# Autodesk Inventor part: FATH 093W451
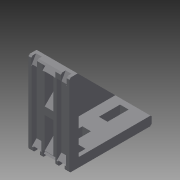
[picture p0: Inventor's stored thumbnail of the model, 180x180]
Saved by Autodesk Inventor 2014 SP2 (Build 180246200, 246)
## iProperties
Created: 2018-10
Part Number: FATH 093W451
Material: Generic
Catalog Web Link: www.cadenas.de
Description: Alu Connection Angle 45-Die-cast Aluminium, Profile 45 and up
Vendor: FATH
Document SubType Name: Modeling
Designer: psadmin
Manufacturer: FATH
Mass: 59.1703 g
Surface Area: 273.577 cm^2
Volume: 59.1703 cm^3
Density: 1 g/cm^3
Appearance: PSOLRGB-175-175-175
Category: PARTsolutions
Company: FATH
Title: FATH 093W451
Author: Cadenas PARTsolutions
Comments: Die-cast Aluminium, Profile 45 and up
PSOL_IDENT_0: {$CADENAS_DATA\23d-libs\fath\zubehoer_alu_sys\aluwinkel\093w451.prj},173 {VTYP=3D},{NB=FATH 093W451}
PSOL_IDENT_1: ,{LINA=FATH 093W451},{NN=Alu Connection Angle 45},{DATE=19.02.2018 15:31:06},{GEOMDATE=21.03.2005},{
PSOL_IDENT_2: VERSION=},{LINEID=570},{WBVAR=},{WBNUMERIC=}  {NB=FATH 093W451},{LINA=FATH 093W451},{KT=DUMMY},{G=Al
PSOL_IDENT_3: uwinkel 86x86x43},{N=ohne},{ARTNR=093W451},{PRTNO=},{NL=0},{NH=0.0},{NHA=0.0}
NN: Aluwinkel 45
NT: Aluminiumdruckguss, ab Profil 45
NB: FATH 093W451
NBSYN: FATH $ARTNR.
LINA: FATH 093W451
G: Aluwinkel 86x86x43
N: ohne
ARTNR: 093W451
SUPPLIER: FATH
ARTICLENO: FATH 093W451
BOMINFO: FATH 093W451
CREATOR: CADENAS GmbH
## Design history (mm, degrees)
sketch "Skizze_1"
  geometry: L1 (8.5, 86)-(1.5, 86); L2 (1.5, 86)-(0, 84.5); L3 (0, 84.5)-(0, 1.5); L4 (1.5, 0)-(84.5, 0); L5 (84.5, 0)-(86, 1.5); L6 (86, 1.5)-(86, 8.5); L7 (86, 8.5)-(8.5, 86); A1 r 1.5 centre (1.5, 1.5) between (0, 1.5) and (1.5, 0)
  constraints: 14 end point, 2 point on circle, 1 centre point
extrude "Extrusion1" join sketch "Skizze_1" stored distance "d0" = 43; taper "d1" = 0 deg
sketch "Skizze_12"
  geometry: L1 (-86, 9.5)-(-10.5, 9.5); L2 (-9.5, 10.5)-(-9.5, 86); L3 (-9.5, 86)-(-86, 9.5); A1 r 1 centre (-10.5, 10.5) between (-10.5, 9.5) and (-9.5, 10.5)
  constraints: 6 end point, 2 point on circle, 1 centre point
extrude "Extrusion2" cut sketch "Skizze_12" distance "d2" = 37; taper "d3" = 0 deg
sketch "Skizze_3"
  geometry: L1 (-2, 79)-(-2, -2); L2 (-2, -2)-(79, -2); L3 (79, -2)-(79, 9.5); L4 (79, 9.5)-(56.876, 9.5); L5 (56.876, 9.5)-(46.376, -1); L6 (46.376, -1)-(39.5, -1); L7 (39.5, -1)-(39.5, 9.5); L8 (39.5, 9.5)-(16.571, 9.5); L9 (16.571, 9.5)-(6.071, -1); L10 (6.071, -1)-(-1, -1); L11 (-1, -1)-(-1, 6.071); L12 (-1, 6.071)-(9.5, 16.571); L13 (9.5, 16.571)-(9.5, 39.5); L14 (9.5, 39.5)-(-1, 39.5); L15 (-1, 39.5)-(-1, 46.376); L16 (-1, 46.376)-(9.5, 56.876); L17 (9.5, 56.876)-(9.5, 79); L18 (9.5, 79)-(-2, 79)
  constraints: 36 end point
extrude "Extrusion3" cut sketch "Skizze_3" stored distance "d4" = 9; taper "d5" = 0 deg
sketch "Skizze_4"
  geometry: L1 (0, 6.788)-(0, 0); L2 (0, 0)-(6.788, 0); L3 (6.788, 0)-(4.101, 2.687); L4 (4.101, 2.687)-(2.687, 1.273); L5 (2.687, 1.273)-(1.273, 2.687); L6 (1.273, 2.687)-(2.687, 4.101); L7 (2.687, 4.101)-(0, 6.788)
  constraints: 14 end point
extrude "Extrusion4" cut sketch "Skizze_4" stored distance "d6" = 13.5; taper "d7" = 0 deg
sketch "Skizze_5"
  geometry: L1 (0, 84.5)-(-4, 84.5); L2 (-4, 84.5)-(-4, -4); L3 (-4, -4)-(84.5, -4); L4 (84.5, -4)-(84.5, 0); L5 (84.5, 0)-(81.672, 2.828); L6 (81.672, 2.828)-(76.843, -2); L7 (76.843, -2)-(-2, -2); L8 (-2, -2)-(-2, 76.843); L9 (-2, 76.843)-(2.828, 81.672); L10 (2.828, 81.672)-(0, 84.5)
  constraints: 20 end point
extrude "Extrusion5" cut sketch "Skizze_5" stored distance "d8" = 13.5; taper "d9" = 0 deg
sketch "Skizze_2"
  geometry: L1 (-20.814, 9.5)-(-9.5, 9.5); L2 (-9.5, 9.5)-(-9.5, 20.814); L3 (-9.5, 20.814)-(-20.814, 9.5)
  constraints: 6 end point
extrude "Extrusion6" join sketch "Skizze_2" stored distance "d10" = 4; taper "d11" = 0 deg
sketch "Skizze_9"
  geometry: L1 (-86, 5)-(-86, -2); L2 (-86, -2)-(2, -2); L3 (2, -2)-(2, 86); L4 (2, 86)-(-5, 86); L5 (-5, 86)-(1, 75.608); L6 (1, 75.608)-(1, -1); L7 (1, -1)-(-75.608, -1); L8 (-75.608, -1)-(-86, 5)
  constraints: 16 end point
extrude "Extrusion7" cut sketch "Skizze_9" stored distance "d12" = 6; taper "d13" = 0 deg
sketch "Skizze_14"
  geometry: L1 (-5.374, 0)-(0, 0); L2 (0, 0)-(0, 5.374); L3 (0, 5.374)-(-5.374, 0)
  constraints: 6 end point
extrude "Extrusion8" cut sketch "Skizze_14" stored distance "d14" = 7; taper "d15" = 0 deg
sketch "Skizze_11"
  geometry: L1 (-79, 0)-(-79, -4); L2 (-79, -4)-(4, -4); L3 (4, -4)-(4, 79); L4 (4, 79)-(0, 79); L5 (0, 79)-(-5, 74); L6 (-5, 74)-(-5, 9.243); L7 (-5, 9.243)-(2, 2.243); L8 (2, 2.243)-(2, -2); L9 (2, -2)-(-2.243, -2); L10 (-2.243, -2)-(-9.243, 5); L11 (-9.243, 5)-(-74, 5); L12 (-74, 5)-(-79, 0)
  constraints: 24 end point
extrude "Extrusion9" cut sketch "Skizze_11" stored distance "d16" = 10; taper "d17" = 0 deg
sketch "Skizze_15"
  geometry: L1 (-86, 5)-(-86, -2); L2 (-86, -2)-(2, -2); L3 (2, -2)-(2, 86); L4 (2, 86)-(-5, 86); L5 (-5, 86)-(1, 75.608); L6 (1, 75.608)-(1, -1); L7 (1, -1)-(-75.608, -1); L8 (-75.608, -1)-(-86, 5)
  constraints: 16 end point
extrude "Extrusion10" cut sketch "Skizze_15" stored distance "d18" = 6; taper "d19" = 0 deg
sketch "Skizze_10"
  geometry: L1 (-5.374, 0)-(0, 0); L2 (0, 0)-(0, 5.374); L3 (0, 5.374)-(-5.374, 0)
  constraints: 6 end point
extrude "Extrusion11" cut sketch "Skizze_10" stored distance "d20" = 7; taper "d21" = 0 deg
sketch "Skizze_13"
  geometry: L1 (-79, 0)-(-79, -4); L2 (-79, -4)-(4, -4); L3 (4, -4)-(4, 79); L4 (4, 79)-(0, 79); L5 (0, 79)-(-5, 74); L6 (-5, 74)-(-5, 9.243); L7 (-5, 9.243)-(2, 2.243); L8 (2, 2.243)-(2, -2); L9 (2, -2)-(-2.243, -2); L10 (-2.243, -2)-(-9.243, 5); L11 (-9.243, 5)-(-74, 5); L12 (-74, 5)-(-79, 0)
  constraints: 24 end point
extrude "Extrusion12" cut sketch "Skizze_13" stored distance "d22" = 10; taper "d23" = 0 deg
body "Solid1"
